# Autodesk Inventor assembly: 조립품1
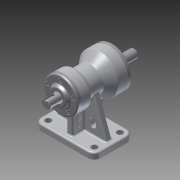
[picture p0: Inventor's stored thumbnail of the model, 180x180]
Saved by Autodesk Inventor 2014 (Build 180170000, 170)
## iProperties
Created: 2015-08
Part Number: 조립품1
Document SubType Name: Assembly
Designer: USER
Author: USER
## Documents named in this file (10)
- C:\Users\USER\Desktop\450805V1034\조립품1.iam
- C:\Users\USER\Desktop\450805V1034\M4x0.5.ipt
- C:\Users\USER\Desktop\450805V1034\뒤커버.ipt
- C:\Users\USER\Desktop\450805V1034\베어링 6203.ipt
- C:\Users\USER\Desktop\450805V1034\베어링 6205.ipt
- C:\Users\USER\Desktop\450805V1034\본체.ipt
- C:\Users\USER\Desktop\450805V1034\앞커버.ipt
- C:\Users\USER\Desktop\450805V1034\오일실 .ipt
- 오일실 .ipt
- C:\Users\USER\Desktop\450805V1034\축.ipt
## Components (10 placed, 1 different names)
1. M4x0.5:1
2. M4x0.5:2
3. M4x0.5:3
4. M4x0.5:4
5. M4x0.5:5
6. M4x0.5:6
7. M4x0.5:7
8. M4x0.5:8
9. M4x0.5:9
10. M4x0.5:10
